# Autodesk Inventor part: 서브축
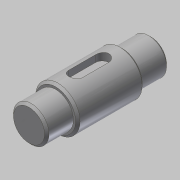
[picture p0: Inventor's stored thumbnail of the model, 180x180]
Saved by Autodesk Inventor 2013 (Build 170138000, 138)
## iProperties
Created: 2019-03
Part Number: 서브축
Material: 강철, 연강
Document SubType Name: Modeling
Designer: mduedu
Density: 1 g/cm^3
Author: mduedu
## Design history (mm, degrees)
sketch "스케치1"
  geometry: L1 (0, 0)-(12, 0); L2 (12, 0)-(12, 8); L3 (12, 8)-(0, 8); L4 (0, 8)-(0, 0); L5 (12, 0)-(42, 0); L6 (42, 0)-(42, 10); L7 (42, 10)-(12, 10); L8 (12, 10)-(12, 0); L9 (42, 0)-(55, 0); L10 (55, 0)-(55, 8); L11 (55, 8)-(42, 8); L12 (42, 8)-(42, 0)
  constraints: 24 end point, 6 parallel, 3 horizontal, 3 perpendicular
  dimensions: "d0" = 16 diameter of L3 L1; "d2" = 20 diameter of L7 L5; "d3" = 16 diameter of L11 L9; "d4" = 12 distance of L2.end L3.end; "d5" = 30 distance of L6.end L7.end; "d6" = 55 distance between parallel lines of L10 L4
revolve "회전1" sketch "스케치1" stored, may be unused: angle "d7" = 90 deg
node "작업 평면1"
sketch "스케치2" dims "d10" = 18
  geometry: L1 (6, -3)-(-6, -3); L2 (-6, -3)-(-6, 3); L3 (-6, 3)-(6, 3); L4 (6, 3)-(6, -3); L5 (15, 10)-(15, -10) reference; 3 further points
  constraints: 8 end point, 2 midpoint, 2 parallel, 2 vertical alignment, 1 horizontal, 1 horizontal alignment, 1 perpendicular, 4 other
  dimensions: "d8" = 6 distance between parallel lines of L3 L1; "d11" = 6 dimension on L5
extrude "돌출1" cut sketch "스케치2" distance "d12" = 3.5; taper "d13" = 0 deg
chamfer "모따기1" distance "d14" = 1; stored, may be unused: second distance "d15" = 2, angle "d16" = 45 deg
chamfer "모따기2" distance "d17" = 1; stored, may be unused: second distance "d18" = 2, angle "d19" = 45 deg
node "솔리드1"
